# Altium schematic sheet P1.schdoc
size 420 x 297 mm; Symbol: Drawing-Symbol_A4; Company: 嘉立创EDA; Version: V1.0; Page Size: A4; @Project Name: 机械臂; @Update Date: 2026-04-11; @Create Date: 2026-04-11; Device: Drawing-Symbol_A4_1; @Board Name: Board1; @Page Name: P1; @Create Time: 14:44:11; @Page Count: 1; @Page No: 1; @Schematic Name: Schematic1; @Update Time: 14:44:11; @Assembly Variant: Basic; Border: 1; Title Block Position: 3; Size: A4; Width: 1655; Height: 1170; Region Start: 1; X Region Count: 6; Y Region Count: 4; Blade Width: 10
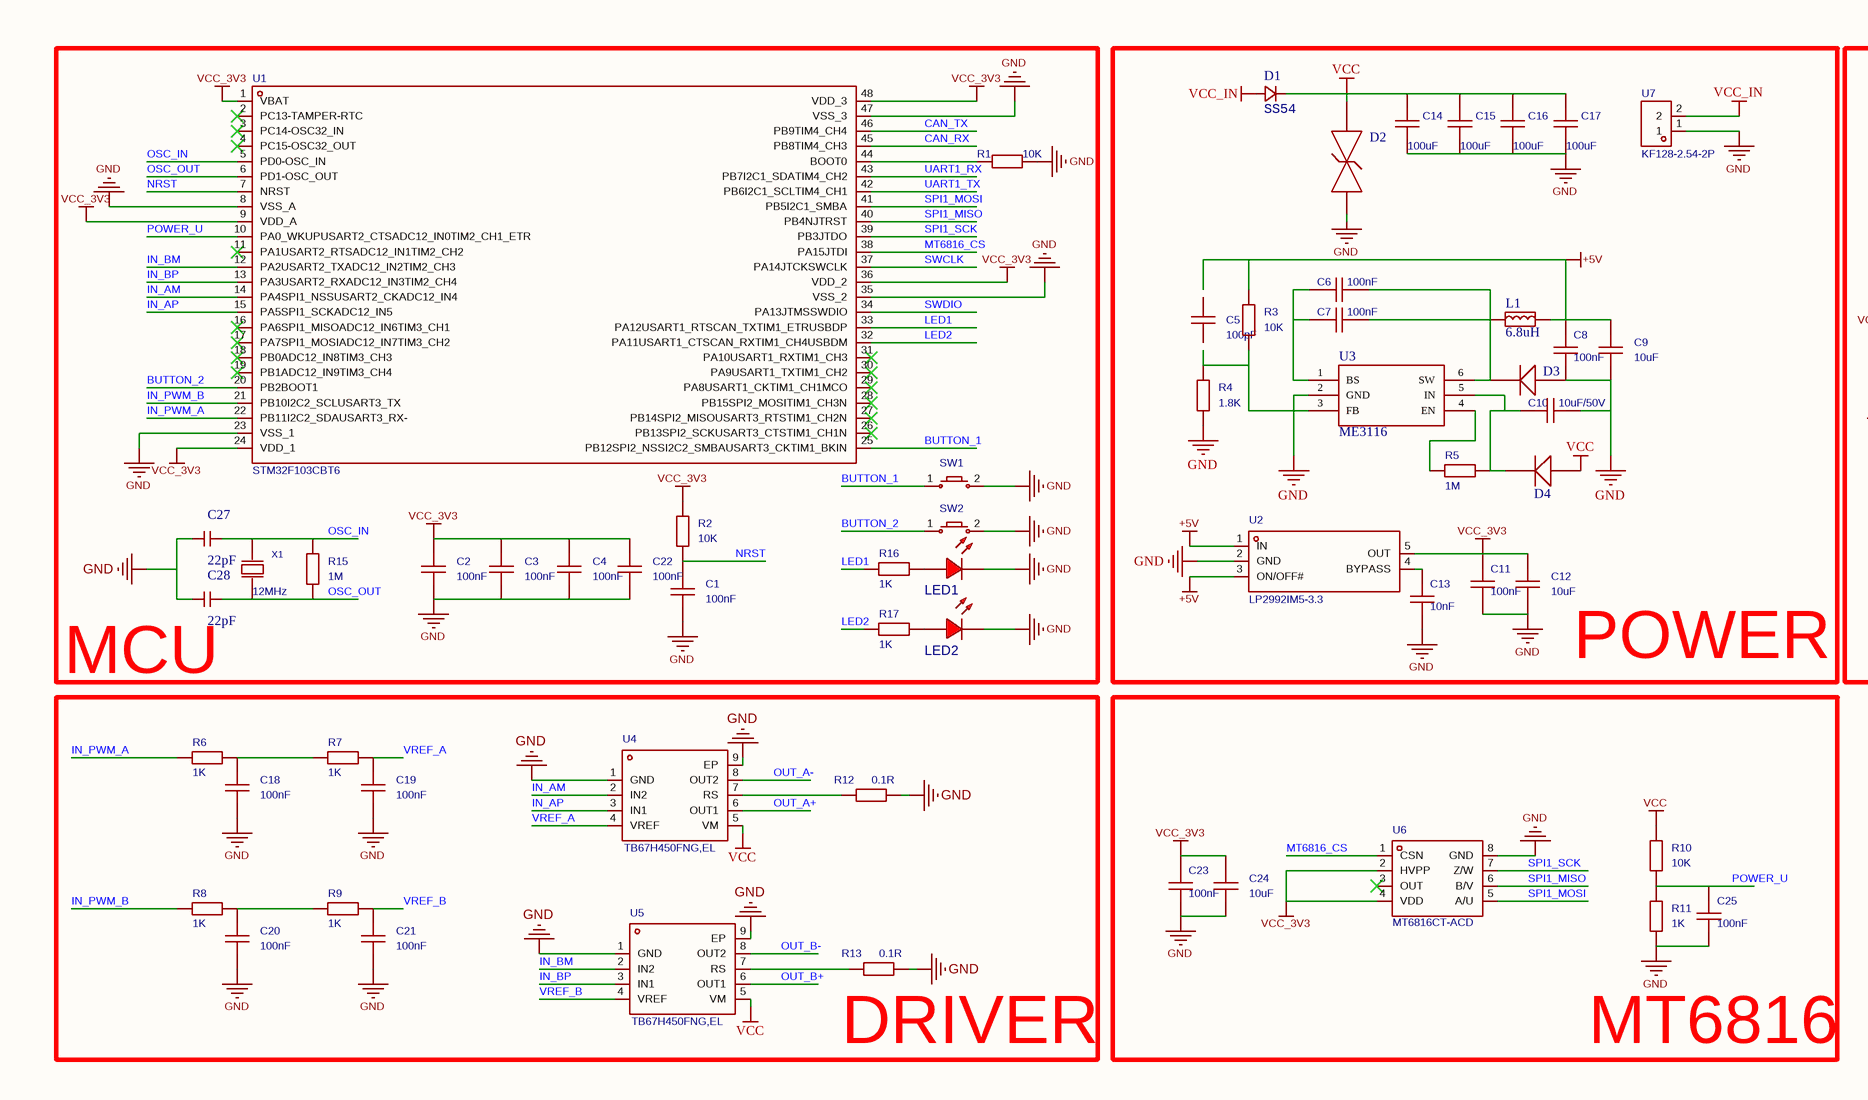
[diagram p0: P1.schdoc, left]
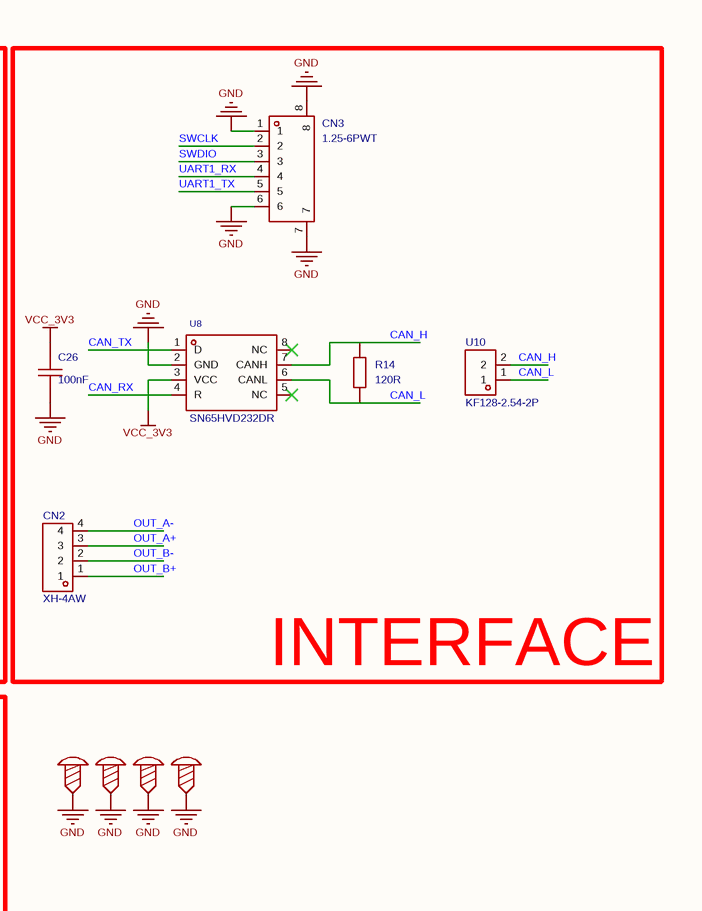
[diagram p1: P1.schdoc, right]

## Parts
C1  100nF  [C0603_2]
C2  100nF  [C0603_2]
C3  100nF  [C0603_2]
C4  100nF  [C0603_2]
C5  100pF  [C0603_2]
C6  100nF  [C0603_2]
C7  100nF  [C0603_2]
C8  100nF  [C0603_2]
C9  10uF  [C0603_2]
C10  10uF/50V  [C0603_2]
C11  100nF  [C0603_2]
C12  10uF  [C0603_2]
C13  10nF  [C0603_2]
C14  100uF  [C1206]
C15  100uF  [C1206]
C16  100uF  [C1206]
C17  100uF  [C1206]
C18  100nF  [C0603_2]
C19  100nF  [C0603_2]
C20  100nF  [C0603_2]
C21  100nF  [C0603_2]
C22  100nF  [C0603_2]
C23  100nF  [C0603_2]
C24  10uF  [C0603_2]
C25  100nF  [C0603_2]
C26  100nF  [C0603_2]
C27  22pF  [C0603_1]
C28  22pF  [C0603_1]
CN2  XH-4AW  [CONN-TH_XH-4AW]
CN3  1.25-6PWT  [CONN-SMD_1.25-6PWT-C2763634]
D1  SS54  [DO-214AC]
D2  SMBJ28CA  [SMBJ-CA_MFG]  (value not drawn)
D3  二极管-5819W  [SOD-323]  (value not drawn)
D4  二极管-5819W  [SOD-323]  (value not drawn)
L1  6.8uH  [IND-201612]
LED1  (no value)  [LED_0603]
LED2  (no value)  [LED_0603]
R1  10K  [R0603_2]
R2  10K  [R0603_2]
R3  10K  [R0603_2]
R4  1.8K  [R0603_2]
R5  1M  [R0603_2]
R6  1K  [R0603_2]
R7  1K  [R0603_2]
R8  1K  [R0603_2]
R9  1K  [R0603_2]
R10  10K  [R0603_2]
R11  1K  [R0603_2]
R12  0.1R  [R1206]
R13  0.1R  [R1206]
R14  120R  [R0603_2]
R15  1M  [R0603_1]
R16  1K  [R0603_2]
R17  1K  [R0603_2]
SCREW1  (no value)  [M3螺丝]
SCREW2  (no value)  [M3螺丝]
SCREW3  (no value)  [M3螺丝]
SCREW4  (no value)  [M3螺丝]
SW1  (no value)  [Key_SMD_3x4x2_1]
SW2  (no value)  [Key_SMD_3x4x2_1]
U1  STM32F103CBT6  [LQFP-48_L7.0-W7.0-P0.50-LS9.0-BL]
U2  LP2992IM5-3.3  [SOT-23-5_L2.9-W1.6-P0.95-LS2.8-BL]
U3  ME3116  [SOT23-6]
U4  TB67H450FNG,EL  [HSOP-8_L5.0-W4.0-P1.27-LS6.2-BL-EP]
U5  TB67H450FNG,EL  [HSOP-8_L5.0-W4.0-P1.27-LS6.2-BL-EP]
U6  MT6816CT-ACD  [SOP-8_L5.0-W4.0-P1.27-LS6.0-BL]
U7  KF128-2.54-2P  [CONN-TH_P2.54_KF128-2.54-2P]
U8  SN65HVD232DR  [SOIC-8_L5.0-W4.0-P1.27-LS6.0-BL]
U10  KF128-2.54-2P  [CONN-TH_P2.54_KF128-2.54-2P]
X1  12MHz  [OSC-SMD_L5.0-W3.2]

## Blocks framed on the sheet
POWER: C5-C17 D1-D4 L1 R3-R5 U2 U3 U7
INTERFACE: C26 CN2 CN3 R14 U8 U10
MT6816: C23-C25 R10 R11 U6

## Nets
+5V: C8.2 C9.2 L1.2 R3.2 U2.1(IN) U2.3(ON/OFF#)
GND: C1.1 C2.1 C3.1 C4.1 C8.1 C9.1 C10.1 C11.1 C12.1 C13.1 C14.1 C15.1 C16.1 C17.1 C18.1 C19.1 C20.1 C21.1 C22.1 C23.1 C24.1 C25.1 C26.1 C27.1 C28.1 CN3.1 CN3.6 CN3.7 CN3.8 D2.2 D3.1(A) LED1.1(C) LED2.1(C) R1.2 R4.1 R11.1 R12.2 R13.2 SCREW1.1 SCREW2.1 SCREW3.1 SCREW4.1 SW1.2 SW2.2 U1.8(VSS_A) U1.23(VSS_1) U1.35(VSS_2) U1.47(VSS_3) U2.2(GND) U3.2(GND) U4.1(GND) U4.9(EP) U5.1(GND) U5.9(EP) U6.8(GND) U7.1 U8.2(GND)
VCC: C14.2 C15.2 C16.2 C17.2 D1.2(K) D2.1 D4.1(A) R10.2 U4.5(VM) U5.5(VM)
VCC_3V3: C2.2 C3.2 C4.2 C11.2 C12.2 C22.2 C23.2 C24.2 C26.2 R2.2 U1.1(VBAT) U1.9(VDD_A) U1.24(VDD_1) U1.36(VDD_2) U1.48(VDD_3) U2.5(OUT) U6.2(HVPP) U6.4(VDD) U8.3(VCC)
VCC_IN: D1.1(A) U7.2
BUTTON_1: SW1.1 U1.25(PB12SPI2_NSSI2C2_SMBAUSART3_CKTIM1_BKIN)
BUTTON_2: SW2.1 U1.20(PB2BOOT1)
CAN_H: R14.2 U8.7(CANH) U10.2
CAN_L: R14.1 U8.6(CANL) U10.1
CAN_RX: U1.45(PB8TIM4_CH3) U8.4(R)
CAN_TX: U1.46(PB9TIM4_CH4) U8.1(D)
IN_AM: U1.14(PA4SPI1_NSSUSART2_CKADC12_IN4) U4.2(IN2)
IN_AP: U1.15(PA5SPI1_SCKADC12_IN5) U4.3(IN1)
IN_BM: U1.12(PA2USART2_TXADC12_IN2TIM2_CH3) U5.2(IN2)
IN_BP: U1.13(PA3USART2_RXADC12_IN3TIM2_CH4) U5.3(IN1)
IN_PWM_A: R6.1 U1.22(PB11I2C2_SDAUSART3_RX-)
IN_PWM_B: R8.1 U1.21(PB10I2C2_SCLUSART3_TX)
LED1: R16.2 U1.33(PA12USART1_RTSCAN_TXTIM1_ETRUSBDP)
LED2: R17.2 U1.32(PA11USART1_CTSCAN_RXTIM1_CH4USBDM)
MT6816_CS: U1.38(PA15JTDI) U6.1(CSN)
NRST: C1.2 R2.1 U1.7(NRST)
OSC_IN: C27.2 R15.1 U1.5(PD0-OSC_IN) X1.2(OSC2)
OSC_OUT: C28.2 R15.2 U1.6(PD1-OSC_OUT) X1.1(OSC1)
OUT_A+: CN2.3 U4.6(OUT1)
OUT_A-: CN2.4 U4.8(OUT2)
OUT_B+: CN2.1 U5.6(OUT1)
OUT_B-: CN2.2 U5.8(OUT2)
POWER_U: C25.2 R10.1 R11.2 U1.10(PA0_WKUPUSART2_CTSADC12_IN0TIM2_CH1_ETR)
SPI1_MISO: U1.40(PB4NJTRST) U6.6(B/V)
SPI1_MOSI: U1.41(PB5I2C1_SMBA) U6.5(A/U)
SPI1_SCK: U1.39(PB3JTDO) U6.7(Z/W)
SWCLK: CN3.2 U1.37(PA14JTCKSWCLK)
SWDIO: CN3.3 U1.34(PA13JTMSSWDIO)
UART1_RX: CN3.4 U1.43(PB7I2C1_SDATIM4_CH2)
UART1_TX: CN3.5 U1.42(PB6I2C1_SCLTIM4_CH1)
VREF_A: C19.2 R7.2 U4.4(VREF)
VREF_B: C21.2 R9.2 U5.4(VREF)
NetC6_1: C6.1 C7.1 U3.1(BS)
NetC6_2: C6.2 C7.2 D3.2(K) L1.1 U3.6(SW)
NetC10_2: C10.2 D4.2(K) R5.1 U3.5(IN)
NetC13_2: C13.2 U2.4(BYPASS)
NetC18_2: C18.2 R6.2 R7.1
NetC20_2: C20.2 R8.2 R9.1
NetLED1_2: LED1.2(A) R16.1
NetLED2_2: LED2.2(A) R17.1
NetR1_1: R1.1 U1.44(BOOT0)
NetR3_1: R3.1 R4.2 U3.3(FB)
NetR5_2: R5.2 U3.4(EN)
NetR12_1: R12.1 U4.7(RS)
NetR13_1: R13.1 U5.7(RS)

Not connected (* = marked no-connect by the designer): C5 1 2; U1 2(PC13-TAMPER-RTC)* 3(PC14-OSC32_IN)* 4(PC15-OSC32_OUT)* 11(PA1USART2_RTSADC12_IN1TIM2_CH2)* 16(PA6SPI1_MISOADC12_IN6TIM3_CH1)* 17(PA7SPI1_MOSIADC12_IN7TIM3_CH2)* 18(PB0ADC12_IN8TIM3_CH3)* 19(PB1ADC12_IN9TIM3_CH4)* 26(PB13SPI2_SCKUSART3_CTSTIM1_CH1N)* 27(PB14SPI2_MISOUSART3_RTSTIM1_CH2N)* 28(PB15SPI2_MOSITIM1_CH3N)* 29(PA8USART1_CKTIM1_CH1MCO)* 30(PA9USART1_TXTIM1_CH2)* 31(PA10USART1_RXTIM1_CH3)*; U6 3(OUT)*; U8 5(NC)* 8(NC)*

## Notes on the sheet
- (near C28) MCU
- (near R13) DRIVER

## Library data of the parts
C1-C4 C6-C13 C18-C21 C23-C26 = CAP_605: Symbol: Capacitance_2; ConvertToPcb: yes; ModelId: ac125912035d415993ca9572d50418b10819f05c4eef4c71ace90d822a990e87; ModelName: C0603_L1.6-W0.8-H0.8; ModelTransform: 62.992,31.496,0,0,0,0,0,0,0
C5 = CL10C101JB8NNNC: 容值:100pF;精度:±5%;额定电压:50V;温度系数:C0G;; Manufacturer: SAMSUNG(三星); Add into BOM: yes; 3D Model: ac125912035d415993ca9572d50418b1; 3D Model Transform: 62.992,31.496,0,0,0,0,0,0,0; Tolerance: ±5%; Voltage Rating: 50V; Temperature Coefficient: C0G; ModelName: C0603_L1.6-W0.8-H0.8
C14-C17 = LMK316B7226ML-TR: Manufacturer: TAIYO YUDEN(太诱); Add into BOM: yes; 3D Model: e4be705b945545a48e666415e3682bd8; 3D Model Transform: 125.984,62.992,0,0,0,0,0,0,0; ModelName: C1206_L3.2-W1.6-H1.3
C22 = CAP_605: Symbol: Capacitance_2; 3D Model: ac125912035d415993ca9572d50418b10819f05c4eef4c71ace90d822a990e87; 3D Model Transform: 62.992,31.496,0,0,0,0,0,0,0; ConvertToPcb: yes; ModelName: C0603_L1.6-W0.8-H0.8
C27 C28 = 100pF: Capacitor; Symbol: -0402_1; Origin Footprint: CAP_0402; Value: 0.1u; AddInBom: yes
CN2 = XH-4AW: 插针结构:1x4P;间距:2.54mm;安装方式:弯插;参考系列:XH;总PIN数:4P;排数:1;每排PIN数:4;行距:-;额定电流:3A;触头材质:黄铜;触头镀层:锡;工作温度:-25℃~+85℃;; Manufacturer: HCTL(华灿天禄); Symbol: XH-4AW_C2908613; AddInBom: yes; ModelId: 82fee406c0fb42748bb7a39a83218b360819f05c4eef4c71ace90d822a990e87; ModelTransform: 492.125,303.936,0,0,0,0,-0.004,-139.091,-118.11; Pins Structure: 1x4P; Pitch: 2.54mm; Reference Series: XH; Number of PINs Per Row: 4; Current Rating: 3A; Voltage Rating: 250V; Plastic Material: PA66; Flame Retardant Rating: UL94V-0; Z-Height of the Board: 5.9mm; Y-Width of Bottom Edge on Board: 7mm
CN3 = 1.25-6PWT: 插针结构:1x6P;间距:1.25mm;安装方式:卧贴;参考系列:PicoBlade(MX 1.25);总PIN数:6P;排数:1;每排PIN数:6;额定电流:1A;触头材质:黄铜;触头镀层:锡;工作温度:-25℃~+85℃;; Manufacturer: FG(富港); AddInBom: yes; ModelId: 3f7d6fb9451e440d83a26d7191e3aa550819f05c4eef4c71ace90d822a990e87; ModelTransform: 496.062,208.661,0,0,0,0,0,-33.465,0; Pins Structure: 1x6P; Pitch: 1.25mm; Number of PINs Per Row: 6; Current Rating: 1A; Voltage Rating: 125V; Z-Height of the Board: 3.6mm; Y-Width of Bottom Edge on Board: 5.25mm
D1 = =value: Diode; Symbol: Diode_SMA; Type: SMA; AddInBom: yes
D2 = SMBJ28CA: AddInBom: yes
D3 D4 = 二极管-5819W: 40V; Symbol: -5819W; AddInBom: yes
L1 = 6.8uH: Symbol: -201612; AddInBom: yes
LED1 LED2 = LED_0603-R: Symbol: LED_R; Convert to PCB: yes; 3D Model: dd8257b0d61a4cd7b68939a056e080950819f05c4eef4c71ace90d822a990e87; 3D Model Transform: 58.72,29.4,22.03,0,0,0,0,0,0; ModelName: LED-0603_R
R1 = Res_605: Symbol: 电阻_2; ConvertToPcb: yes; ModelId: fc143cca1e79419f9cd78b61e9279f080819f05c4eef4c71ace90d822a990e87; ModelName: R0603; ModelTransform: 31.8897,63.7794,0,90,0,0,0,0,0
R2-R11 R14 R16 R17 = Res_605: Symbol: 电阻_2; 3D Model: fc143cca1e79419f9cd78b61e9279f080819f05c4eef4c71ace90d822a990e87; 3D Model Transform: 31.8897,63.7794,0,90,0,0,0,0,0; ConvertToPcb: yes; ModelName: R0603
R12 R13 = Res_1206: Symbol: 电阻_2; 3D Model: 89a1f13db2384da588040e0b3c55bf660819f05c4eef4c71ace90d822a990e87; 3D Model Transform: 125.984,62.992,0,0,0,0,0,0,0; AddInBom: yes; ModelName: R1206_L3.2-W1.6-H0.6
R15 = Res_604: Symbol: 电阻_1; 3D Model: 8176a32bb9f4431db75ab5f6460c2416; 3D Model Transform: 63,31.5,20.1,0,0,0,0,0,0; ConvertToPcb: yes; ModelName: R0603_L1.6-W0.8-H0.5
SCREW1-SCREW4 = M3螺丝: Symbol: 螺丝孔; ConvertToPcb: yes
SW1 SW2 = Key_SMD_3x4x2_1: Symbol: 轻触按键x2_1; ConvertToPcb: yes; ModelId: 63599cce708d48afbce1b0db003544770819f05c4eef4c71ace90d822a990e87; ModelName: SW-SMD_L4.0-W2.9-H2-LS5.0; ModelTransform: 196.85,114.17,79.13,0,0,0,0,0,0
U1 = STM32F103CBT6: CPU内核:ARM Cortex-M3;CPU最大主频:72MHz;工作电压范围:2V~3.6V;程序存储容量:128KB;程序存储器类型:FLASH;RAM总容量:20KB;GPIO端口数量:37;; Manufacturer: ST(意法半导体); 3D Model: 093be70396ff421eb2cdb946d5311efc; 3D Model Transform: 354.331,354.331,0,0,0,0,0,0,0; CPU Maximum Speed: 72MHz; Program Storage Size: 128KB; Program Memory Type: FLASH; RAM Size: 20KB; GPIO Ports Number: 37; ADC (Bit): 12bit; Universal Serial Bus: 有; Peripheral/Function: DMA；片载温度传感器；PWM; AddInBom: yes; ModelName: LQFP-48_L7.0-W7.0-H1.4-LS9.0-P0.50
U2 = LP2992IM5-3.3: 输出类型:固定;输出极性:正;最大输入电压:16V;输出电压:3.3V;输出电流:250mA;电源纹波抑制比(PSRR):45dB@(1kHz);; Manufacturer: TI(德州仪器); 3D Model: 018c57e721114987ae90467fe9f1d259; 3D Model Transform: 114.96,110.236,0,0,0,0,0,0,0; Output Type: 固定; Output Polarity: 正; Number of Outputs: 1; Maximum Input Voltage: 16V; Output Voltage: 3.3V; Dropout Voltage: 850mV@(250mA); Quiescent Current (Ground Current): 95uA; Output Current: 250mA; AddInBom: yes
U3 = ME3116: DC-DC; AddInBom: yes
U4 U5 = TB67H450FNG,EL: Manufacturer: TOSHIBA(东芝); 3D Model: aaf4e90098584f278f891a4d5ef3600d; 3D Model Transform: 248.031,192.913,0,90,0,0,0.0005,0.0005,0; AddInBom: yes; ModelName: HSOP-8_L4.9-W3.9-H1.8-LS6.0-P1.27
U6 = MT6816CT-ACD: AB=1024线，Z=4LSB，PWM=1KHz; Manufacturer: MagnTek(麦歌恩); 3D Model: a3315c1c78f949e6bb82c6eaca1c53c7; 3D Model Transform: 244.094,196.85,0,90,0,0,0,0,0; AddInBom: yes; ModelName: SOP-8_L5.0-W4.0-H1.8-LS6.2-P1.27
U7 U10 = KF128-2.54-2P: 结构:1x2P;间距:2.54mm;颜色:绿色;安装方式:直插;额定电流:8A;额定电压:130V;排数:1;线规 - AWG:18~26;线规 - 平方毫米:1;每排PIN数:2;工作温度范围:-40℃~+105℃;; Manufacturer: KEFA(科发); 3D Model: 38629642489141faa979009e13fb8a570819f05c4eef4c71ace90d822a990e87; 3D Model Transform: 200,248.031,0,0,0,0,0,-5.906,-137.795; Structure: 1x2P; Pitch: 2.54mm; Current Rating (Max): 8A; Voltage Rating (Max): 130V; Wire Gauge - AWG: 18~26; Wire Gauge - mm2: 1; Number of PINs Per Row: 2; AddInBom: yes
U8 = SN65HVD232DR: 类型:收发器;数据速率:1Mbps;; Manufacturer: TI(德州仪器); 3D Model: e81d2f7d937b4a6ab1dca543ff5d56a4; 3D Model Transform: 189.751,236.22,0,0,0,0,-0.0005,0.0005,0; Data Rate: 1Mbps; Supply Voltage: 3V~3.6V; AddInBom: yes; ModelName: SOIC-8_L4.9-W3.9-H1.7-LS6.0-P1.27
X1 = TAXM12M2QLFCDT1T: 频率:12MHz;频率公差:±30ppm;负载电容:20pF;; Manufacturer: TAE(雅晶鑫); Symbol: SMD-5032_2P 12M 20pf 30ppm; Add into BOM: yes; 3D Model: 36c8b961b9064b60a7c920ab5154e867; 3D Model Transform: 196.85,126.023,0,0,0,0,0,0,0; Crystal Type: 贴片无源晶振; Frequency Tolerance: ±30ppm; Load Capacitance: 20pF; Equivalent Series Resistance (ESR): 30Ω; ModelName: OSC-SMD_L5.0-W3.2-H1.4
